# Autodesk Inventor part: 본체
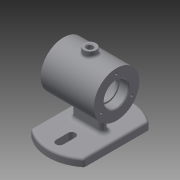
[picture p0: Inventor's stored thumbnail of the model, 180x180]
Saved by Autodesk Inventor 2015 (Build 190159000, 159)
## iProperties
Created: 2017-12
Part Number: 본체
Material: 일반
Document SubType Name: Modeling
Designer: 2-PC10
Density: 1 g/cm^3
Appearance: 기본값
Author: 2-PC10
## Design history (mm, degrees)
sketch "스케치1"
  geometry: L1 (35, -42.426)-(35, 42.426); L2 (-35, 42.426)-(-35, -42.426); A1 r 55 centre (0, 0) between (-35, -42.426) and (35, -42.426); A2 r 55 centre (0, 0) between (35, 42.426) and (-35, 42.426); 4 further points
  constraints: 4 end point, 4 point on circle, 2 centre point, 2 horizontal alignment, 2 midpoint, 1 coincident, 1 parallel
  dimensions: "d1" = 70 distance between parallel lines of L1 L2; "d2" = 55 radius of A2; "d3" = 55 radius of A1; "d5" = 84.85281 distance of L1.start L1.end
extrude "돌출1" new body sketch "스케치1" distance "d6" = 10; taper "d7" = 0 deg
sketch "스케치2"
  geometry: L1 (-42.426, 0)-(42.426, 0) reference; C1 r 30 at (0, 62); 2 further points
  constraints: 1 centre point, 1 midpoint, 1 vertical alignment
  dimensions: "d8" = 60 diameter of C1; "d9" = 62 distance from line of L1 C1.centre
extrude "돌출2" join sketch "스케치2" stored distance "d10" = 70; taper "d11" = 0 deg
sketch "스케치3"
  geometry: L1 (-15, 5)-(15, 5); L2 (20, 0)-(20, 0); L3 (15, -5)-(-15, -5); L4 (-20, 0)-(-20, 0); L5 (-20, 5)-(20, -5); L6 (20, 5)-(-20, -5); A1 r 5 centre (-15, 0) between (-15, 5) and (-20, 0); A2 r 5 centre (-15, 0) between (-20, 0) and (-15, -5); A3 r 5 centre (15, 0) between (20, 0) and (15, 5); A4 r 5 centre (15, 0) between (15, -5) and (20, 0); 1 further point
  constraints: 12 end point, 8 point on circle, 8 point on line, 8 tangent, 4 centre point, 3 equal radius, 2 midpoint, 2 parallel, 1 horizontal, 1 perpendicular
  dimensions: "d12" = 10 distance between parallel lines of L3 L1; "d13" = 5 radius of A1; "d14" = 30 distance of A3.centre A1.centre
extrude "돌출3" join sketch "스케치3" stored distance "d15" = 70; taper "d16" = 0 deg
hole "구멍1" diameter "d19" = 28; stored, may be unused: countersink angle "d23" = 90 deg, drill point angle "d25" = 0 deg; dims "d17" = 10, "d18" = 10, "d20" = 6, "d21" = 4, "d22" = 2, "d24" = 8
hole "구멍2" diameter "d28" = 32; stored, may be unused: countersink angle "d32" = 90 deg, drill point angle "d34" = 0 deg; dims "d26" = 10, "d27" = 10, "d29" = 6, "d30" = 4, "d31" = 2, "d33" = 12
sketch "스케치4"
  geometry: C1 r 25 at (0, 62); C2 r 30 at (0, 62) reference; 1 further point
  constraints: 1 centre point, 1 concentric
  dimensions: "d35" = 50 diameter of C1
extrude "돌출4" cut sketch "스케치4" stored distance "d36" = 40; taper "d37" = 0 deg
node "작업 평면1"
sketch "스케치5"
  geometry: L1 (35, -30)-(35, 30) reference; C1 r 8 at (0, 0); 1 further point
  constraints: 1 centre point, 1 coincident
  dimensions: "d39" = 16 diameter of C1; "d40" = 35 distance from line of L1 C1.centre
extrude "돌출5" join sketch "스케치5" stored distance "d41" = 40; taper "d42" = 0 deg
hole "구멍3" diameter "d45" = 8; stored, may be unused: countersink angle "d49" = 90 deg, drill point angle "d51" = 0 deg; dims "d43" = 10, "d44" = 10, "d46" = 6, "d47" = 4, "d48" = 2, "d50" = 40
sketch "스케치6" dims "d52" = 46
  geometry: C1 r 30 at (0, 0) reference; 3 further points
  constraints: 2 horizontal alignment, 3 other
hole "구멍4" sketch "스케치6" at (-23, 0) diameter "d53" = 3.242; stored, may be unused: countersink angle "d57" = 90 deg, drill point angle "d59" = 118 deg; dims "d54" = 8, "d55" = 4, "d56" = 2, "d58" = 10
sketch "스케치7"
  geometry: L1 (0, -45)-(0, -19); L2 (5, -40)-(5, -24); L3 (-5, -24)-(-5, -40); L4 (0, 19)-(0, 45); L5 (5, 24)-(5, 40); L6 (-5, 40)-(-5, 24); A1 r 5 centre (0, -40) between (-5, -40) and (5, -40); A2 r 5 centre (0, -24) between (5, -24) and (-5, -24); A3 r 5 centre (0, 24) between (-5, 24) and (5, 24); A4 r 5 centre (0, 40) between (5, 40) and (-5, 40); 3 further points
  constraints: 16 end point, 12 point on circle, 8 tangent, 6 point on line, 4 centre point, 2 midpoint, 2 parallel, 1 vertical, 1 vertical alignment
  dimensions: "d63" = 10 distance between parallel lines of L3 L2; "d64" = 10 distance between parallel lines of L6 L5; "d65" = 16 distance of A2.centre A1.centre; "d66" = 16 distance of A4.centre A3.centre; "d67" = 24 distance of point (0, 0) A2.centre; "d68" = 24 distance of point (0, 0) A3.centre
extrude "돌출6" cut sketch "스케치7" stored distance "d69" = 40; taper "d70" = 0 deg
chamfer "모따기1" distance "d71" = 1; stored, may be unused: second distance "d72" = 2, angle "d73" = 45 deg
fillet "모깎기1" dims "d74" = 3
fillet "모깎기2" dims "d75" = 3
fillet "모깎기3" dims "d76" = 5
fillet "모깎기4" dims "d77" = 3
fillet "모깎기5" dims "d78" = 0.3
node "작업 평면2"
sketch "스케치8"
  geometry: L1 (-26, 5)-(26, 5); L2 (26, 5)-(26, -5); L3 (26, -5)-(-26, -5); L4 (-26, -5)-(-26, 5); L5 (-26, 0)-(26, 0); L6 (0, 5)-(0, -5); L7 (35, -30)-(35, 30) reference; L8 (-35, 30)-(-35, -30) reference; 1 further point
  constraints: 4 end point, 4 midpoint, 2 other
  dimensions: "d79" = 52 distance between parallel lines of L4 L2; "d80" = 10 distance between parallel lines of L3 L1; "d85" = 35 distance between parallel lines of L8 L6; "d86" = 30 distance from line of L8.start L5
feature "엠보싱1" sketch "스케치8" dims "d83" = 0.5, "d84" = 0
sketch "스케치9"
  geometry: 1 further point
node "솔리드1"
mirror "대칭1"
pattern_circular "원형 패턴1" dims angle "d61" = 360 deg
mirror "대칭2"
other parameters: "d38" = 99
